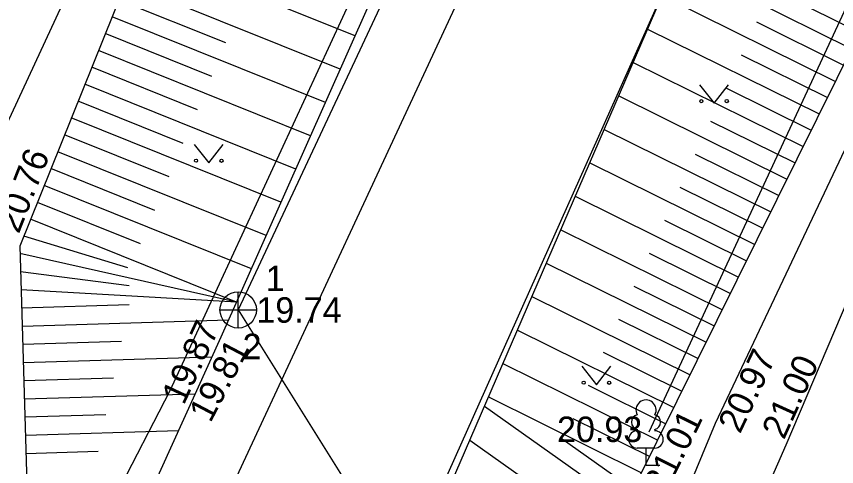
# Model space of a CAD drawing. Extents: x 714391 to 714584, y 6589993 to 6590151.
# Drawn here: x 714448.93 to 714471.46, y 6590114.75 to 6590127.12 of the extents above; entities that cross this region are included whole.
import ezdxf

# ---------------------------------------------------------------- set-up
doc = ezdxf.new("R2010")
doc.units = 0
for name, color, linetype in [('HALJASTUS', 7, 'Continuous'), ('KKAEV', 7, 'Continuous'), ('KORGUS', 7, 'Continuous'), ('KTRASS', 7, 'Continuous'), ('MPKAABEL', 7, 'Continuous'), ('PUU', 7, 'Continuous'), ('RELJEEF', 7, 'Continuous'), ('SITRASS', 7, 'Continuous'), ('SKTRASS', 7, 'Continuous'), ('TEE', 7, 'Continuous'), ('TORU NR', 7, 'Continuous')]:
    doc.layers.add(name, color=color, linetype=linetype)

msp = doc.modelspace()

# ---------------------------------------------------------------- linework, layer by layer
at = {"layer": 'HALJASTUS'}
for p, q in [((714466.315, 6590115.707), (714477.77, 6590140.433)), ((714467.69, 6590125.245), (714468.095, 6590124.74)), ((714468.095, 6590124.74), (714468.49, 6590125.245)), ((714453.812, 6590123.606), (714454.217, 6590123.101)), ((714454.217, 6590123.101), (714454.612, 6590123.606)), ((714464.46, 6590117.509), (714464.865, 6590117.004)), ((714464.865, 6590117.004), (714465.26, 6590117.509))]:
    msp.add_line(p, q, dxfattribs=at)
for centre, radius in [((714467.742, 6590124.795), 0.0428), ((714468.442, 6590124.795), 0.0452), ((714453.864, 6590123.157), 0.0428), ((714454.564, 6590123.157), 0.0452), ((714464.512, 6590117.059), 0.0428), ((714465.212, 6590117.059), 0.0452)]:
    msp.add_circle(centre, radius, dxfattribs=at)
at = {"layer": 'KKAEV'}
for p, q in [((714455.022, 6590118.56), (714455.022, 6590119.56)), ((714454.522, 6590119.06), (714455.522, 6590119.06))]:
    msp.add_line(p, q, dxfattribs=at)
msp.add_circle((714455.022, 6590119.06), 0.5, dxfattribs=at)
at = {"layer": 'KTRASS'}
for p, q in [((714465.284, 6590140.994), (714455.022, 6590119.06)), ((714455.022, 6590119.06), (714467.741, 6590098.726)), ((714455.245, 6590118.654), (714455.241, 6590118.661))]:
    msp.add_line(p, q, dxfattribs=at)
at = {"layer": 'MPKAABEL'}
msp.add_lwpolyline([(714394.611, 6589992.711), (714400.19, 6590004.938), (714412.114, 6590031.265), (714423.696, 6590056.183), (714434.84, 6590082.35), (714435.599, 6590083.495), (714435.59, 6590083.97), (714441.1, 6590097.08), (714442.02, 6590098.72), (714442.75, 6590099.35), (714444.22, 6590100.41), (714445.54, 6590101.3), (714446.63, 6590102.41), (714450.168, 6590111.053), (714453.153, 6590116.846), (714463.66, 6590139.57), (714466.53, 6590147), (714468.444, 6590151.075)], dxfattribs=at)
at = {"layer": 'PUU'}
for p, q in [((714465.984, 6590115.768), (714465.984, 6590115.738)), ((714466.464, 6590115.768), (714466.464, 6590115.738)), ((714466.464, 6590115.263), (714465.984, 6590115.263)), ((714466.224, 6590114.788), (714466.224, 6590115.263)), ((714466.604, 6590114.788), (714466.224, 6590114.788))]:
    msp.add_line(p, q, dxfattribs=at)
for centre, radius, start, end in [((714466.224, 6590116.308), 0.277, 332.5799, 207.4201), ((714466.034, 6590115.976), 0.212, 105.2441, 257.079), ((714466.414, 6590115.976), 0.212, 282.921, 74.7559), ((714465.986, 6590115.501), 0.237, 90, 270), ((714466.461, 6590115.501), 0.237, 270, 90)]:
    msp.add_arc(centre, radius, start, end, dxfattribs=at)
at = {"layer": 'RELJEEF'}
for p, q in [((714458.233, 6590126.587), (714452.305, 6590128.971)), ((714467.063, 6590128.615), (714471.871, 6590126.235)), ((714457.826, 6590125.672), (714451.932, 6590128.043)), ((714466.666, 6590127.696), (714471.427, 6590125.339)), ((714469.677, 6590127.879), (714472.092, 6590126.683)), ((714454.684, 6590126.397), (714451.745, 6590127.579)), ((714457.419, 6590124.758), (714451.558, 6590127.115)), ((714466.268, 6590126.776), (714470.983, 6590124.442)), ((714469.256, 6590126.971), (714471.649, 6590125.787)), ((714454.294, 6590125.476), (714451.372, 6590126.651)), ((714457.012, 6590123.844), (714451.185, 6590126.188)), ((714468.836, 6590126.063), (714471.205, 6590124.891)), ((714453.903, 6590124.555), (714450.999, 6590125.724)), ((714465.871, 6590125.857), (714470.54, 6590123.546)), ((714456.605, 6590122.93), (714450.812, 6590125.26)), ((714468.415, 6590125.156), (714470.761, 6590123.994)), ((714453.513, 6590123.634), (714450.625, 6590124.796)), ((714465.473, 6590124.938), (714470.096, 6590122.65)), ((714456.198, 6590122.016), (714450.439, 6590124.332)), ((714467.995, 6590124.248), (714470.318, 6590123.098)), ((714453.123, 6590122.713), (714450.252, 6590123.868)), ((714465.076, 6590124.019), (714469.652, 6590121.754)), ((714455.791, 6590121.101), (714450.066, 6590123.404)), ((714467.574, 6590123.34), (714469.874, 6590122.202)), ((714452.733, 6590121.792), (714449.879, 6590122.94)), ((714464.678, 6590123.1), (714469.209, 6590120.858)), ((714455.384, 6590120.187), (714449.693, 6590122.477)), ((714467.154, 6590122.433), (714469.431, 6590121.306)), ((714464.281, 6590122.181), (714468.765, 6590119.961)), ((714452.343, 6590120.871), (714449.506, 6590122.013)), ((714454.977, 6590119.273), (714449.319, 6590121.549)), ((714466.733, 6590121.525), (714468.987, 6590120.409)), ((714463.884, 6590121.262), (714468.322, 6590119.065)), ((714451.995, 6590120.216), (714449.133, 6590121.085)), ((714454.977, 6590119.273), (714449.029, 6590120.606)), ((714466.313, 6590120.617), (714468.543, 6590119.513)), ((714463.486, 6590120.343), (714467.878, 6590118.169)), ((714452.029, 6590119.72), (714449.044, 6590120.106)), ((714454.977, 6590119.273), (714449.059, 6590119.607)), ((714465.892, 6590119.71), (714468.1, 6590118.617)), ((714463.089, 6590119.424), (714467.434, 6590117.273)), ((714452.028, 6590119.195), (714449.074, 6590119.107)), ((714454.756, 6590118.776), (714449.089, 6590118.607)), ((714465.472, 6590118.802), (714467.656, 6590117.721)), ((714462.691, 6590118.505), (714466.991, 6590116.377)), ((714451.817, 6590118.188), (714449.103, 6590118.107)), ((714454.3, 6590117.762), (714449.118, 6590117.608)), ((714465.051, 6590117.894), (714467.212, 6590116.825)), ((714462.294, 6590117.586), (714466.547, 6590115.48)), ((714451.602, 6590117.181), (714449.133, 6590117.108)), ((714464.631, 6590116.987), (714466.769, 6590115.928)), ((714453.84, 6590116.748), (714449.148, 6590116.608)), ((714461.896, 6590116.667), (714466.103, 6590114.584)), ((714461.788, 6590116.417), (714465.561, 6590113.746)), ((714451.387, 6590116.174), (714449.163, 6590116.108)), ((714464.21, 6590116.079), (714466.325, 6590115.032)), ((714453.381, 6590115.734), (714449.178, 6590115.608)), ((714463.921, 6590115.52), (714465.85, 6590114.155)), ((714461.383, 6590115.479), (714464.984, 6590112.93)), ((714451.172, 6590115.168), (714449.193, 6590115.109))]:
    msp.add_line(p, q, dxfattribs=at)
for points in [[(714461.322, 6590149.285), (714459.685, 6590146.474), (714455.021, 6590135.724), (714449.023, 6590120.812), (714449.282, 6590112.11)], [(714458.683, 6590107.808), (714459.134, 6590108.095), (714463.55, 6590110.904), (714465.985, 6590114.345), (714472.574, 6590127.656), (714478.445, 6590140.562)]]:
    msp.add_lwpolyline(points, dxfattribs=at)
at = {"layer": 'SITRASS'}
msp.add_line((714445.318, 6590093.669), (714471.983, 6590151.075), dxfattribs=at)
at = {"layer": 'SKTRASS'}
msp.add_line((714458.254, 6590108.91), (714474.359, 6590144.932), dxfattribs=at)
at = {"layer": 'TEE'}
for points in [[(714461.172, 6590151.075), (714459.316, 6590147.116), (714455.509, 6590138.934), (714446.669, 6590119.883), (714437.663, 6590099.797), (714438.254, 6590097.927), (714442.53, 6590099.149)], [(714450.542, 6590109.47), (714454.553, 6590118.32), (714462.112, 6590135.302), (714467.698, 6590147.41), (714469.311, 6590151.075)], [(714583.92, 6590101.143), (714565.419, 6590101.225), (714549.748, 6590101.3), (714530.696, 6590101.382), (714516.957, 6590101.382), (714497.906, 6590101.442), (714488.527, 6590101.467), (714476.238, 6590101.479), (714465.964, 6590101.492), (714465.149, 6590101.593), (714461.989, 6590102.308), (714461.271, 6590102.628), (714460.534, 6590103.105), (714459.97, 6590103.737), (714459.406, 6590104.596), (714458.782, 6590106.528), (714458.59, 6590109.02), (714468.756, 6590132.53), (714474.437, 6590144.828), (714474.939, 6590145.152), (714475.17, 6590145.792), (714474.999, 6590146.077), (714477.095, 6590151.075)], [(714483.807, 6590151.075), (714479.211, 6590140.446), (714473.212, 6590126.702), (714468.119, 6590115.935), (714463.556, 6590104.916), (714462.138, 6590102.626), (714461.947, 6590102.318)], [(714485.932, 6590151.075), (714482.73, 6590143.88), (714480.61, 6590139.609), (714475.962, 6590129.206), (714470.061, 6590115.343), (714465.263, 6590104.4), (714464.405, 6590102.057), (714464.305, 6590101.784)]]:
    msp.add_lwpolyline(points, dxfattribs=at)

# ---------------------------------------------------------------- texts
at = {"layer": 'KORGUS'}
for s, rotation, p in [('20.76', 68.5146, (714448.996, 6590121.13)), ('19.87', 64.9652, (714453.528, 6590116.422)), ('19.81', 62.3056, (714454.26, 6590115.935)), ('20.97', 64.6702, (714468.807, 6590115.634)), ('21.00', 65.5332, (714470.014, 6590115.471)), ('21.01', 63.5437, (714466.755, 6590113.979))]:
    msp.add_text(s, height=0.7, rotation=rotation, dxfattribs=at).set_placement(p)
for s, p in [('19.74', (714455.521, 6590118.707)), ('20.93', (714463.78, 6590115.429))]:
    msp.add_text(s, height=0.7, dxfattribs=at).set_placement(p)
at = {"layer": 'TORU NR'}
for s, p in [('1', (714455.775, 6590119.574)), ('2', (714455.143, 6590117.705))]:
    msp.add_text(s, height=0.7, dxfattribs=at).set_placement(p)

doc.saveas('drawing.dxf')
